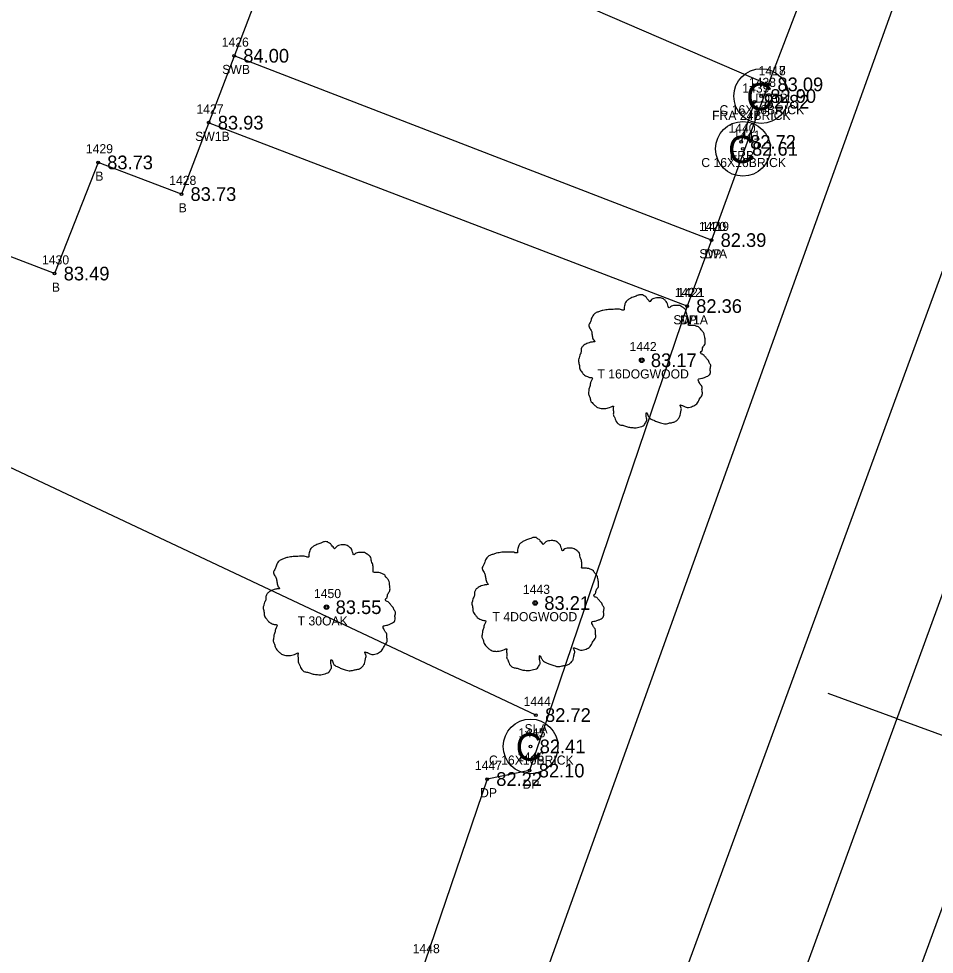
# Model space of a CAD drawing. Extents: x 2139392 to 2143384, y 505395 to 510520.
# Drawn here: x 2141070.2 to 2141170.6, y 509599 to 509701.6 of the extents above; entities that cross this region are included whole.
import ezdxf

# ---------------------------------------------------------------- set-up
doc = ezdxf.new("R2010")
doc.units = 0
for name, color, linetype in [('RD_EX_Bldg', 7, 'Continuous'), ('RD_EX_Bldg_txCode', 7, 'Continuous'), ('RD_EX_BldgApp', 7, 'Continuous'), ('RD_EX_BldgApp_txCode', 7, 'Continuous'), ('RD_EX_Conc', 7, 'Continuous'), ('RD_EX_Conc_txCode', 7, 'Continuous'), ('RD_EX_DR_Pipe', 7, 'Continuous'), ('RD_EX_Driveway', 7, 'Continuous'), ('RD_EX_Driveway_txCode', 7, 'Continuous'), ('RD_EX_Fence_Other', 7, 'Continuous'), ('RD_EX_Fence_Other_txCode', 7, 'Continuous'), ('RD_EX_Road', 7, 'Continuous'), ('RD_EX_TX_Bldg_ELEV', 7, 'Continuous'), ('RD_EX_TX_BldgApp_ELEV', 7, 'Continuous'), ('RD_EX_TX_Conc_ELEV', 7, 'Continuous'), ('RD_EX_TX_Driveway_ELEV', 7, 'Continuous'), ('RD_EX_TX_Fence_Other_ELEV', 7, 'Continuous'), ('RD_EX_TX_VEG_ELEV', 7, 'Continuous'), ('RD_EX_VEG', 7, 'Continuous'), ('RD_EX_VEG_txCode', 7, 'Continuous'), ('RD_HC_Cl', 7, 'Continuous'), ('RD_HC_Data_Tic', 7, 'Continuous'), ('RD_SMD_Locator', 7, 'Continuous')]:
    doc.layers.add(name, color=color, linetype=linetype)

msp = doc.modelspace()

# ---------------------------------------------------------------- linework, layer by layer
at = {"layer": 'RD_EX_Bldg'}
msp.add_lwpolyline([(2141096.39, 509731.86), (2141090.96, 509716.83), (2141099.81, 509713.25), (2141088.03, 509682.4), (2141078.89, 509685.87), (2141074.12, 509673.68), (2141050.78, 509682.61), (2141073.04, 509740.79), (2141096.39, 509731.86)], dxfattribs=at)
at = {"layer": 'RD_EX_BldgApp'}
for centre in [(2141151.63, 509693.15), (2141149.63, 509687.36), (2141126.33, 509621.81)]:
    msp.add_circle(centre, 3, dxfattribs=at)
at = {"layer": 'RD_EX_Conc'}
for p, q in [((2141146.18, 509677.35), (2141093.82, 509697.57)), ((2141143.5, 509670.11), (2141091.02, 509690.23))]:
    msp.add_line(p, q, dxfattribs=at)
msp.add_lwpolyline([(2141078.88, 509757.3), (2141090.54, 509749.9), (2141097.06, 509743.27), (2141102.31, 509735.14), (2141100.25, 509729.73), (2141095.79, 509718.74), (2141100.82, 509716.73), (2141152.41, 509694.43)], dxfattribs=at)
at = {"layer": 'RD_EX_DR_Pipe'}
msp.add_line((2141176.12, 509730.76), (2141125.75, 509590.72), dxfattribs=at)
at = {"layer": 'RD_EX_Driveway'}
msp.add_lwpolyline([(2141191.47, 509727.8), (2141181.9, 509720.35), (2141172.39, 509721.32), (2141164.15, 509724.67), (2141156.72, 509705.7), (2141152.41, 509694.43), (2141146.18, 509677.35), (2141143.5, 509670.11), (2141126.23, 509619.16), (2141121.57, 509618.23), (2141114.74, 509598.13), (2141140.09, 509588.3)], dxfattribs=at)
at = {"layer": 'RD_EX_Fence_Other'}
msp.add_line((2141150.9, 509692.53), (2141149.42, 509688.12), dxfattribs=at)
at = {"layer": 'RD_EX_Road'}
for points in [[(2141389.23, 510293.58), (2141374.66, 510243.58), (2141359.1, 510192.72), (2141341.17, 510140.58), (2141322.74, 510087.97), (2141303.61, 510035.12), (2141287.18, 509990.16), (2141276.99, 509962.02), (2141248.91, 509884.35), (2141213.37, 509787.47), (2141207.76, 509772.94), (2141199.35, 509749.36), (2141191.47, 509727.8), (2141175.93, 509686.04), (2141140.09, 509588.3), (2141106.08, 509494.11), (2141096.82, 509469.24), (2141063.82, 509378.98), (2141052.52, 509348.48), (2141043.48, 509323.88)], [(2141412.62, 510288.46), (2141398.29, 510238.16), (2141381.65, 510185.39), (2141379.05, 510176.51), (2141367.08, 510141.57), (2141363.58, 510131.95), (2141345.23, 510080.36), (2141326.05, 510027.03), (2141308.64, 509979.4), (2141271.24, 509876.37), (2141240, 509789.51), (2141233.78, 509773.43), (2141223.56, 509746.41), (2141212.18, 509714.93), (2141204.36, 509694.36), (2141197.99, 509676.56), (2141193.66, 509664.6), (2141161.61, 509577.24), (2141123.75, 509473.61), (2141115.5, 509450.65), (2141102.09, 509414.61), (2141086.27, 509371.27), (2141050.42, 509272.83)]]:
    msp.add_lwpolyline(points, dxfattribs=at)
at = {"layer": 'RD_EX_VEG'}
msp.add_line((2141126.92, 509625.25), (2141040.92, 509665.71), dxfattribs=at)
for centre, radius in [((2141138.53, 509664.17), 0.25), ((2141138.52, 509664.15), 0.0001), ((2141103.95, 509637.08), 0.25), ((2141126.84, 509637.54), 0.25), ((2141126.83, 509637.52), 0.0001), ((2141103.94, 509637.06), 0.0001)]:
    msp.add_circle(centre, radius, dxfattribs=at)
for points in [[(2141138.67, 509671.34), (2141138.37, 509671.36), (2141138.04, 509671.26), (2141137.79, 509671.16), (2141137.57, 509671.09), (2141137.34, 509670.99), (2141137.04, 509670.81), (2141136.82, 509670.61), (2141136.69, 509670.36), (2141136.64, 509670.14), (2141136.59, 509669.86), (2141136.59, 509669.69), (2141136.47, 509669.66), (2141136.32, 509669.69), (2141136.07, 509669.76), (2141135.82, 509669.76), (2141135.57, 509669.76), (2141135.22, 509669.74), (2141134.87, 509669.74), (2141134.59, 509669.69), (2141134.27, 509669.64), (2141133.89, 509669.51), (2141133.54, 509669.39), (2141133.24, 509669.14), (2141132.99, 509668.66), (2141132.87, 509668.31), (2141132.72, 509668.06), (2141132.87, 509667.62), (2141133.04, 509667.27), (2141133.07, 509667.07), (2141133.14, 509666.64), (2141133.24, 509666.42), (2141133.37, 509666.22), (2141133.29, 509666.19), (2141132.92, 509666.14), (2141132.62, 509666.04), (2141132.19, 509665.82), (2141131.97, 509665.59), (2141131.87, 509665.27), (2141131.84, 509664.92), (2141131.74, 509664.72), (2141131.67, 509664.44), (2141131.64, 509664.37), (2141131.59, 509664.04), (2141131.69, 509663.59), (2141131.72, 509663.24), (2141131.84, 509663.02), (2141131.99, 509662.84), (2141132.17, 509662.59), (2141132.57, 509662.37), (2141132.89, 509662.27), (2141133.09, 509662.24), (2141132.92, 509661.74), (2141132.87, 509661.39), (2141132.74, 509660.99), (2141132.74, 509660.92), (2141132.69, 509660.44), (2141132.84, 509660.12), (2141132.92, 509659.74), (2141133.09, 509659.52), (2141133.37, 509659.22), (2141133.69, 509658.99), (2141134.19, 509658.87), (2141134.59, 509658.89), (2141135.17, 509659.07), (2141135.42, 509659.14), (2141135.39, 509658.97), (2141135.42, 509658.59), (2141135.42, 509658.17), (2141135.57, 509657.84), (2141135.67, 509657.57), (2141135.82, 509657.32), (2141136.14, 509657.09), (2141136.54, 509657.02), (2141136.97, 509656.87), (2141137.42, 509656.79), (2141137.92, 509656.77), (2141138.52, 509656.92), (2141138.79, 509657.04), (2141138.89, 509657.22), (2141139.09, 509657.59), (2141139.04, 509657.82), (2141139.07, 509658.42), (2141139.17, 509658.24), (2141139.34, 509657.89), (2141139.84, 509657.59), (2141140.24, 509657.42), (2141140.72, 509657.27), (2141141.02, 509657.19), (2141141.49, 509657.27), (2141141.87, 509657.34), (2141142.24, 509657.47), (2141142.54, 509657.74), (2141142.72, 509658.02), (2141142.77, 509658.29), (2141142.84, 509658.67), (2141142.89, 509658.84)], [(2141142.89, 509658.84), (2141142.82, 509659.02), (2141142.77, 509659.27), (2141142.84, 509659.24), (2141143.01, 509659.19), (2141143.29, 509659.07), (2141143.51, 509658.99), (2141143.84, 509659.02), (2141144.11, 509659.12), (2141144.56, 509659.39), (2141144.84, 509659.87), (2141145.11, 509660.27), (2141145.19, 509660.59), (2141145.14, 509660.82), (2141145.11, 509661.32), (2141144.91, 509661.57), (2141144.86, 509661.69), (2141144.76, 509662.09), (2141144.84, 509662.14), (2141145.11, 509662.19), (2141145.49, 509662.32), (2141145.76, 509662.44), (2141145.99, 509662.62), (2141146.06, 509662.84), (2141146.04, 509663.24), (2141146.09, 509663.64), (2141146.01, 509663.79), (2141145.91, 509663.94), (2141145.84, 509664.14), (2141145.69, 509664.29), (2141145.59, 509664.44), (2141145.49, 509664.54), (2141145.36, 509664.69), (2141145.19, 509664.82), (2141145.04, 509664.87), (2141144.99, 509665.02), (2141145.14, 509665.22), (2141145.19, 509665.32), (2141145.21, 509665.54), (2141145.44, 509665.89), (2141145.49, 509666.29), (2141145.44, 509666.72), (2141145.39, 509666.99), (2141145.24, 509667.27), (2141145.04, 509667.52), (2141144.91, 509667.69), (2141144.74, 509667.82), (2141144.41, 509667.94), (2141144.16, 509667.99), (2141143.81, 509667.99), (2141143.61, 509668.04), (2141143.64, 509668.09), (2141143.64, 509668.24), (2141143.64, 509668.51), (2141143.56, 509668.96), (2141143.41, 509669.46), (2141143.41, 509669.49), (2141143.31, 509669.74), (2141143.09, 509669.94), (2141142.91, 509670.04), (2141142.72, 509670.16), (2141142.47, 509670.19), (2141142.17, 509670.19), (2141141.89, 509670.14), (2141141.69, 509670.04), (2141141.52, 509669.91), (2141141.44, 509670.06), (2141141.34, 509670.36), (2141141.29, 509670.51), (2141141.14, 509670.69), (2141140.92, 509670.89), (2141140.47, 509671.01), (2141139.84, 509670.94), (2141139.54, 509670.74), (2141139.39, 509670.56), (2141139.34, 509670.69), (2141139.14, 509670.89), (2141139.04, 509671.06), (2141138.87, 509671.19), (2141138.72, 509671.29), (2141138.62, 509671.34)], [(2141126.97, 509644.71), (2141126.67, 509644.73), (2141126.35, 509644.63), (2141126.1, 509644.53), (2141125.87, 509644.46), (2141125.65, 509644.36), (2141125.35, 509644.18), (2141125.12, 509643.98), (2141125, 509643.73), (2141124.95, 509643.51), (2141124.9, 509643.23), (2141124.9, 509643.06), (2141124.77, 509643.03), (2141124.62, 509643.06), (2141124.37, 509643.13), (2141124.12, 509643.13), (2141123.87, 509643.13), (2141123.52, 509643.11), (2141123.17, 509643.11), (2141122.9, 509643.06), (2141122.57, 509643.01), (2141122.2, 509642.88), (2141121.85, 509642.76), (2141121.55, 509642.51), (2141121.3, 509642.03), (2141121.18, 509641.68), (2141121.03, 509641.43), (2141121.18, 509640.98), (2141121.35, 509640.63), (2141121.38, 509640.43), (2141121.45, 509640.01), (2141121.55, 509639.78), (2141121.67, 509639.58), (2141121.6, 509639.56), (2141121.23, 509639.51), (2141120.93, 509639.41), (2141120.5, 509639.18), (2141120.28, 509638.96), (2141120.18, 509638.63), (2141120.15, 509638.28), (2141120.05, 509638.08), (2141119.98, 509637.81), (2141119.95, 509637.73), (2141119.9, 509637.41), (2141120, 509636.96), (2141120.03, 509636.61), (2141120.15, 509636.38), (2141120.3, 509636.21), (2141120.48, 509635.96), (2141120.88, 509635.73), (2141121.2, 509635.63), (2141121.4, 509635.61), (2141121.23, 509635.11), (2141121.18, 509634.76), (2141121.05, 509634.36), (2141121.05, 509634.29), (2141121, 509633.81), (2141121.15, 509633.49), (2141121.23, 509633.11), (2141121.4, 509632.89), (2141121.67, 509632.59), (2141122, 509632.36), (2141122.5, 509632.24), (2141122.9, 509632.26), (2141123.47, 509632.44), (2141123.72, 509632.51), (2141123.7, 509632.34), (2141123.72, 509631.96), (2141123.72, 509631.54), (2141123.87, 509631.21), (2141123.97, 509630.94), (2141124.12, 509630.69), (2141124.45, 509630.46), (2141124.85, 509630.39), (2141125.27, 509630.24), (2141125.72, 509630.16), (2141126.22, 509630.14), (2141126.82, 509630.29), (2141127.1, 509630.41), (2141127.2, 509630.59), (2141127.4, 509630.96), (2141127.35, 509631.19), (2141127.37, 509631.79), (2141127.47, 509631.61), (2141127.65, 509631.26), (2141128.15, 509630.96), (2141128.55, 509630.79), (2141129.02, 509630.64), (2141129.32, 509630.56), (2141129.8, 509630.64), (2141130.17, 509630.71), (2141130.55, 509630.84), (2141130.85, 509631.11), (2141131.02, 509631.39), (2141131.07, 509631.66), (2141131.15, 509632.04), (2141131.2, 509632.21)], [(2141131.2, 509632.21), (2141131.12, 509632.39), (2141131.07, 509632.64), (2141131.15, 509632.61), (2141131.32, 509632.56), (2141131.6, 509632.44), (2141131.82, 509632.36), (2141132.15, 509632.39), (2141132.42, 509632.49), (2141132.87, 509632.76), (2141133.14, 509633.24), (2141133.42, 509633.64), (2141133.49, 509633.96), (2141133.44, 509634.19), (2141133.42, 509634.69), (2141133.22, 509634.94), (2141133.17, 509635.06), (2141133.07, 509635.46), (2141133.14, 509635.51), (2141133.42, 509635.56), (2141133.79, 509635.68), (2141134.07, 509635.81), (2141134.29, 509635.98), (2141134.37, 509636.21), (2141134.34, 509636.61), (2141134.39, 509637.01), (2141134.32, 509637.16), (2141134.22, 509637.31), (2141134.14, 509637.51), (2141133.99, 509637.66), (2141133.89, 509637.81), (2141133.79, 509637.91), (2141133.67, 509638.06), (2141133.49, 509638.18), (2141133.34, 509638.23), (2141133.29, 509638.38), (2141133.44, 509638.58), (2141133.49, 509638.68), (2141133.52, 509638.91), (2141133.74, 509639.26), (2141133.79, 509639.66), (2141133.74, 509640.08), (2141133.69, 509640.36), (2141133.54, 509640.63), (2141133.34, 509640.88), (2141133.22, 509641.06), (2141133.04, 509641.18), (2141132.72, 509641.31), (2141132.47, 509641.36), (2141132.12, 509641.36), (2141131.92, 509641.41), (2141131.95, 509641.46), (2141131.95, 509641.61), (2141131.95, 509641.88), (2141131.87, 509642.33), (2141131.72, 509642.83), (2141131.72, 509642.86), (2141131.62, 509643.11), (2141131.4, 509643.31), (2141131.22, 509643.41), (2141131.02, 509643.53), (2141130.77, 509643.56), (2141130.47, 509643.56), (2141130.2, 509643.51), (2141130, 509643.41), (2141129.82, 509643.28), (2141129.75, 509643.43), (2141129.65, 509643.73), (2141129.6, 509643.88), (2141129.45, 509644.06), (2141129.22, 509644.26), (2141128.77, 509644.38), (2141128.15, 509644.31), (2141127.85, 509644.11), (2141127.7, 509643.93), (2141127.65, 509644.06), (2141127.45, 509644.26), (2141127.35, 509644.43), (2141127.17, 509644.56), (2141127.02, 509644.66), (2141126.92, 509644.71)], [(2141104.09, 509644.24), (2141103.79, 509644.27), (2141103.46, 509644.17), (2141103.21, 509644.07), (2141102.99, 509643.99), (2141102.76, 509643.89), (2141102.46, 509643.72), (2141102.24, 509643.52), (2141102.11, 509643.27), (2141102.06, 509643.04), (2141102.01, 509642.77), (2141102.01, 509642.59), (2141101.89, 509642.57), (2141101.74, 509642.59), (2141101.49, 509642.67), (2141101.24, 509642.67), (2141100.99, 509642.67), (2141100.64, 509642.64), (2141100.29, 509642.64), (2141100.01, 509642.59), (2141099.69, 509642.54), (2141099.31, 509642.42), (2141098.96, 509642.29), (2141098.66, 509642.04), (2141098.41, 509641.57), (2141098.29, 509641.22), (2141098.14, 509640.97), (2141098.29, 509640.52), (2141098.46, 509640.17), (2141098.49, 509639.97), (2141098.56, 509639.55), (2141098.66, 509639.32), (2141098.79, 509639.12), (2141098.71, 509639.1), (2141098.34, 509639.05), (2141098.04, 509638.95), (2141097.61, 509638.72), (2141097.39, 509638.5), (2141097.29, 509638.17), (2141097.26, 509637.82), (2141097.16, 509637.62), (2141097.09, 509637.35), (2141097.06, 509637.27), (2141097.01, 509636.95), (2141097.11, 509636.5), (2141097.14, 509636.15), (2141097.26, 509635.92), (2141097.41, 509635.75), (2141097.59, 509635.5), (2141097.99, 509635.27), (2141098.31, 509635.17), (2141098.51, 509635.15), (2141098.34, 509634.65), (2141098.29, 509634.3), (2141098.16, 509633.9), (2141098.16, 509633.82), (2141098.11, 509633.35), (2141098.26, 509633.02), (2141098.34, 509632.65), (2141098.51, 509632.42), (2141098.79, 509632.12), (2141099.11, 509631.9), (2141099.61, 509631.77), (2141100.01, 509631.8), (2141100.59, 509631.97), (2141100.84, 509632.05), (2141100.81, 509631.87), (2141100.84, 509631.5), (2141100.84, 509631.07), (2141100.99, 509630.75), (2141101.09, 509630.47), (2141101.24, 509630.23), (2141101.56, 509630), (2141101.96, 509629.93), (2141102.39, 509629.78), (2141102.84, 509629.7), (2141103.34, 509629.68), (2141103.94, 509629.83), (2141104.21, 509629.95), (2141104.31, 509630.13), (2141104.51, 509630.5), (2141104.46, 509630.72), (2141104.49, 509631.32), (2141104.59, 509631.15), (2141104.76, 509630.8), (2141105.26, 509630.5), (2141105.66, 509630.33), (2141106.13, 509630.18), (2141106.43, 509630.1), (2141106.91, 509630.18), (2141107.28, 509630.25), (2141107.66, 509630.38), (2141107.96, 509630.65), (2141108.13, 509630.92), (2141108.18, 509631.2), (2141108.26, 509631.57), (2141108.31, 509631.75)], [(2141108.31, 509631.75), (2141108.23, 509631.92), (2141108.18, 509632.17), (2141108.26, 509632.15), (2141108.43, 509632.1), (2141108.71, 509631.97), (2141108.93, 509631.9), (2141109.26, 509631.92), (2141109.53, 509632.02), (2141109.98, 509632.3), (2141110.26, 509632.77), (2141110.53, 509633.17), (2141110.61, 509633.5), (2141110.56, 509633.72), (2141110.53, 509634.22), (2141110.33, 509634.47), (2141110.28, 509634.6), (2141110.18, 509635), (2141110.26, 509635.05), (2141110.53, 509635.1), (2141110.91, 509635.22), (2141111.18, 509635.35), (2141111.41, 509635.52), (2141111.48, 509635.75), (2141111.46, 509636.15), (2141111.51, 509636.55), (2141111.43, 509636.7), (2141111.33, 509636.85), (2141111.26, 509637.05), (2141111.11, 509637.2), (2141111.01, 509637.35), (2141110.91, 509637.45), (2141110.78, 509637.6), (2141110.61, 509637.72), (2141110.46, 509637.77), (2141110.41, 509637.92), (2141110.56, 509638.12), (2141110.61, 509638.22), (2141110.63, 509638.45), (2141110.86, 509638.8), (2141110.91, 509639.2), (2141110.86, 509639.62), (2141110.81, 509639.9), (2141110.66, 509640.17), (2141110.46, 509640.42), (2141110.33, 509640.6), (2141110.16, 509640.72), (2141109.83, 509640.85), (2141109.58, 509640.9), (2141109.23, 509640.9), (2141109.03, 509640.95), (2141109.06, 509641), (2141109.06, 509641.15), (2141109.06, 509641.42), (2141108.98, 509641.87), (2141108.83, 509642.37), (2141108.83, 509642.39), (2141108.73, 509642.64), (2141108.51, 509642.84), (2141108.33, 509642.94), (2141108.13, 509643.07), (2141107.88, 509643.09), (2141107.58, 509643.09), (2141107.31, 509643.04), (2141107.11, 509642.94), (2141106.93, 509642.82), (2141106.86, 509642.97), (2141106.76, 509643.27), (2141106.71, 509643.42), (2141106.56, 509643.59), (2141106.33, 509643.79), (2141105.88, 509643.92), (2141105.26, 509643.84), (2141104.96, 509643.64), (2141104.81, 509643.47), (2141104.76, 509643.59), (2141104.56, 509643.79), (2141104.46, 509643.97), (2141104.29, 509644.09), (2141104.14, 509644.19), (2141104.04, 509644.24)]]:
    msp.add_spline(points, degree=3, dxfattribs=at)
at = {"layer": 'RD_HC_Cl'}
msp.add_line((2141333.53, 510081.69), (2140670.51, 508268.37), dxfattribs=at)
at = {"layer": 'RD_HC_Data_Tic'}
for q in [(2141158.98, 509627.6), (2141174.01, 509622.11)]:
    msp.add_line((2141166.49, 509624.86), q, dxfattribs=at)
at = {"layer": 'RD_SMD_Locator'}
for centre in [(2141093.82, 509697.57), (2141152.41, 509694.43), (2141152.41, 509694.43), (2141150.9, 509692.53), (2141151.63, 509693.15), (2141091.02, 509690.23), (2141149.42, 509688.12), (2141149.63, 509687.36), (2141078.89, 509685.87), (2141088.03, 509682.4), (2141146.18, 509677.35), (2141146.18, 509677.35), (2141074.12, 509673.68), (2141143.5, 509670.11), (2141143.5, 509670.11), (2141138.53, 509664.17), (2141126.84, 509637.54), (2141103.95, 509637.08), (2141126.92, 509625.25), (2141126.33, 509621.81), (2141126.23, 509619.16), (2141121.57, 509618.23)]:
    msp.add_circle(centre, 0.15, dxfattribs=at)

# ---------------------------------------------------------------- texts
at = {"layer": 'RD_EX_Bldg_txCode'}
for s, p in [('1429', (2141077.55, 509686.87)), ('B', (2141078.59, 509683.87)), ('1428', (2141086.69, 509683.4)), ('B', (2141087.73, 509680.4)), ('1430', (2141072.74, 509674.68)), ('B', (2141073.82, 509671.68))]:
    msp.add_text(s, height=1, dxfattribs=at).set_placement(p)
at = {"layer": 'RD_EX_BldgApp'}
for p in [(2141150, 509691.59), (2141148, 509685.8), (2141124.7, 509620.25)]:
    msp.add_text('C', height=3, dxfattribs=at).set_placement(p)
at = {"layer": 'RD_EX_BldgApp_txCode'}
for s, p in [('1438', (2141150.28, 509694.15)), ('C 16X16BRICK', (2141147.06, 509691.15)), ('1441', (2141148.56, 509688.36)), ('C 16X16BRICK', (2141145.06, 509685.36)), ('1445', (2141124.99, 509622.81)), ('C 16X16BRICK', (2141121.77, 509619.81))]:
    msp.add_text(s, height=1, dxfattribs=at).set_placement(p)
at = {"layer": 'RD_EX_Conc_txCode'}
for s, p in [('1426', (2141092.45, 509698.57)), ('SWB', (2141092.51, 509695.57)), ('1418', (2141151.35, 509695.43)), ('DC1B', (2141150.99, 509692.43)), ('1427', (2141089.68, 509691.23)), ('SW1B', (2141089.54, 509688.23)), ('1420', (2141144.8, 509678.35)), ('SWA', (2141144.85, 509675.35)), ('1422', (2141142.15, 509671.11)), ('SW1A', (2141142, 509668.11))]:
    msp.add_text(s, height=1, dxfattribs=at).set_placement(p)
at = {"layer": 'RD_EX_Driveway_txCode'}
for s, p in [('1417', (2141151.35, 509695.43)), ('DP', (2141151.63, 509692.43)), ('1419', (2141145.12, 509678.35)), ('DP', (2141145.4, 509675.35)), ('1421', (2141142.44, 509671.11)), ('DP', (2141142.72, 509668.11)), ('1446', (2141124.86, 509620.16)), ('1447', (2141120.22, 509619.23)), ('DP', (2141125.45, 509617.16)), ('DP', (2141120.79, 509616.23)), ('1448', (2141113.4, 509599.13))]:
    msp.add_text(s, height=1, dxfattribs=at).set_placement(p)
at = {"layer": 'RD_EX_Fence_Other_txCode'}
for s, p in [('1439', (2141149.56, 509693.53)), ('FRA 24BRICK', (2141146.24, 509690.53)), ('1440', (2141148.04, 509689.12)), ('FRB', (2141148.19, 509686.12))]:
    msp.add_text(s, height=1, dxfattribs=at).set_placement(p)
at = {"layer": 'RD_EX_TX_Bldg_ELEV'}
for s, p in [('83.73', (2141079.89, 509685.12)), ('83.73', (2141089.03, 509681.65)), ('83.49', (2141075.12, 509672.93))]:
    msp.add_text(s, height=1.5, dxfattribs=at).set_placement(p)
at = {"layer": 'RD_EX_TX_BldgApp_ELEV'}
for s, p in [('82.90', (2141152.63, 509692.4)), ('82.61', (2141150.63, 509686.61)), ('82.41', (2141127.33, 509621.06))]:
    msp.add_text(s, height=1.5, dxfattribs=at).set_placement(p)
at = {"layer": 'RD_EX_TX_Conc_ELEV'}
for s, p in [('84.00', (2141094.82, 509696.82)), ('83.09', (2141153.41, 509693.68)), ('83.93', (2141092.02, 509689.48)), ('82.39', (2141147.18, 509676.6)), ('82.36', (2141144.5, 509669.36))]:
    msp.add_text(s, height=1.5, dxfattribs=at).set_placement(p)
at = {"layer": 'RD_EX_TX_Driveway_ELEV'}
for s, p in [('83.09', (2141153.41, 509693.68)), ('82.39', (2141147.18, 509676.6)), ('82.36', (2141144.5, 509669.36)), ('82.10', (2141127.23, 509618.41)), ('82.22', (2141122.57, 509617.48))]:
    msp.add_text(s, height=1.5, dxfattribs=at).set_placement(p)
at = {"layer": 'RD_EX_TX_Fence_Other_ELEV'}
for s, p in [('82.82', (2141151.9, 509691.78)), ('82.72', (2141150.42, 509687.37))]:
    msp.add_text(s, height=1.5, dxfattribs=at).set_placement(p)
at = {"layer": 'RD_EX_TX_VEG_ELEV'}
for s, p in [('83.17', (2141139.53, 509663.42)), ('83.21', (2141127.84, 509636.79)), ('83.55', (2141104.95, 509636.33)), ('82.72', (2141127.92, 509624.5))]:
    msp.add_text(s, height=1.5, dxfattribs=at).set_placement(p)
at = {"layer": 'RD_EX_VEG_txCode'}
for s, p in [('1442', (2141137.19, 509665.17)), ('T 16DOGWOOD', (2141133.67, 509662.17)), ('1443', (2141125.49, 509638.54)), ('1450', (2141102.57, 509638.08)), ('T 4DOGWOOD', (2141122.16, 509635.54)), ('T 30OAK', (2141100.78, 509635.08)), ('1444', (2141125.57, 509626.25)), ('SLA', (2141125.67, 509623.25))]:
    msp.add_text(s, height=1, dxfattribs=at).set_placement(p)

doc.saveas('drawing.dxf')
